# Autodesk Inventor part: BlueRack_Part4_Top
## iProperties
Shininess: 64.0
Length Units: 11272
Angle Units: 11279
Time Units: 11290
Mass Units: 11286
Length Display Precision: 3
Angle Display Precision: 2
Compacted: True
Part Number: BlueRack_Part4_Top
Document SubType Name: Modeling
Created: 2004-12
Designer: John Blackburn
Material: Steel, Mild
Manufacturer: Standard
Standards Organization: Custom
Density: 0.0
Volumn: 0.0
Area: 0.0
PropertySet Name: Model Information
Control State: 0
Master: False
Checked Out: False
Author: John Blackburn
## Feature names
1. Extrusion1
2. Extrusion2
3. Hole1
4. Rectangular Pattern1
